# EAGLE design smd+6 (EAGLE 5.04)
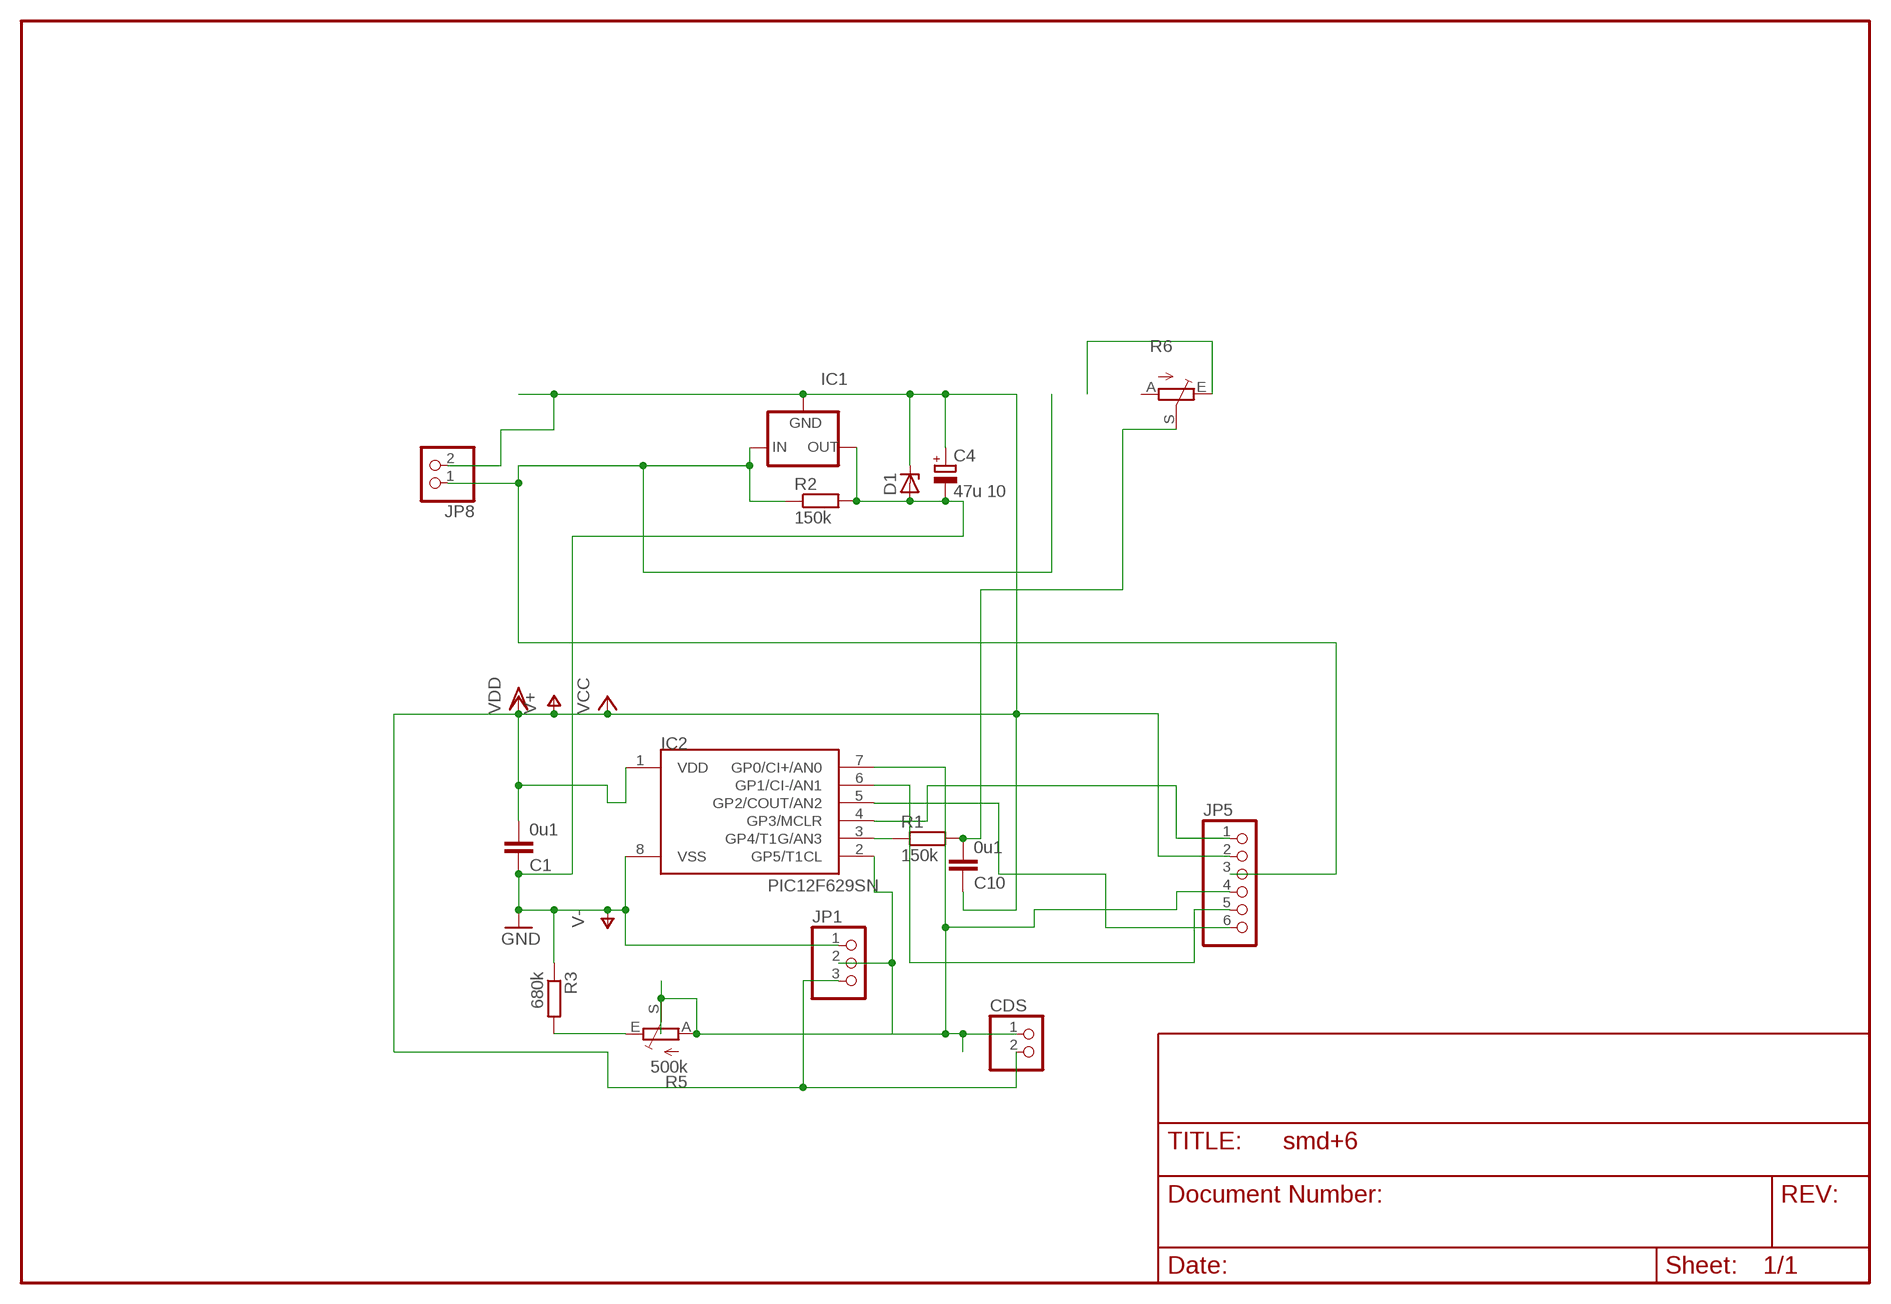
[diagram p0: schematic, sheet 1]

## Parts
C1  0u1  C-EUC1206  [C1206]
C4  47u 10  CPOL-EUE2.5-6  [E2,5-6]
C10  0u1  C-EUC1206  [C1206]
CDS  PINHD-1X2  [1X02]
D1  ZENER-DIODESOT23  [SOT23]
IC1  79LXX  [79LXX]
IC2  PIC12F629SN  [SO-08]
JP1  PINHD-1X3  [1X03]
JP5  PINHD-1X6  [1X06]
JP8  PINHD-1X2  [1X02]
R1  150k  R-EU_R0805  [R0805]
R2  150k  R-EU_0204/2V  [0204V]
R3  680k  R-EU_R1206  [R1206]
R5  500k  TRIM_EU-CA6V  [CA6V]
R6  TRIM_EU-CA6V  [CA6V]

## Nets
CDS: IC2.2(GP5/T1CL) JP1.2
N$1: C10.2 R1.2 R6.S
N$2: IC2.5(GP2/COUT/AN2) JP5.6
N$3: IC2.4(GP3/MCLR) JP5.1
N$4: CDS.1 IC2.7(GP0/CI+/AN0) JP5.4 R5.A R5.S
N$5: R3.2 R5.E
N$7: R6.E
N$8: IC2.3(GP4/T1G/AN3) R1.1
N$10: IC1.IN JP5.3 JP8.1 R2.1
N$15: IC2.6(GP1/CI-/AN1) JP5.5
V+: C1.2 C4.+ C10.1 CDS.2 D1.3(C) IC1.GND IC2.1(VDD) JP1.3 JP5.2 JP8.2 ; supply symbol labelled VCC, VDD
V-: C1.1 C4.- D1.1(A) IC1.OUT IC2.8(VSS) JP1.1 R2.2 R3.1 ; supply symbol labelled GND
Unconnected: R6.A

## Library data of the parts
C1 C10 = rcl:C-EU: CAPACITOR, European symbol
C4 = rcl:CPOL-EU: POLARIZED CAPACITOR, European symbol
CDS JP8 = pinhead:PINHD-1X2: PIN HEADER
D1 = diode-1:ZENER-DIODE: Z-Diode
IC1 = v-reg:79LXX: VOLTAGE REGULATOR
IC2 = microchip-3:PIC12F6*: uPC nW 1k Program Flash memory 2x Timer Comparator 10b A/D converter/ 4xIN
JP1 = pinhead(2):PINHD-1X3: PIN HEADER
JP5 = pinhead(2):PINHD-1X6: PIN HEADER
R1-R3 = rcl:R-EU_: RESISTOR, European symbol
R5 R6 = pot:TRIM_EU-: POTENTIOMETER

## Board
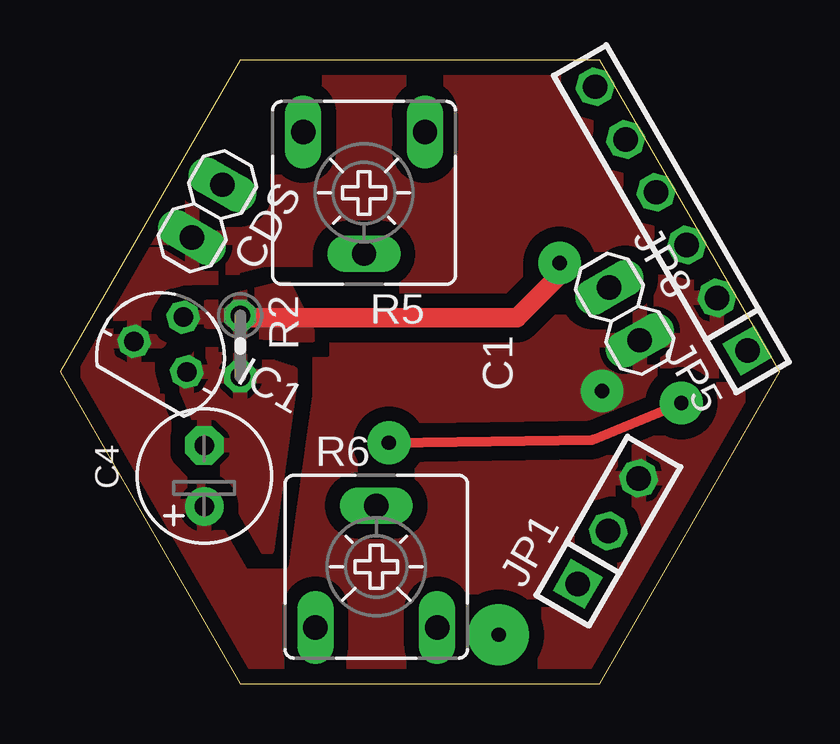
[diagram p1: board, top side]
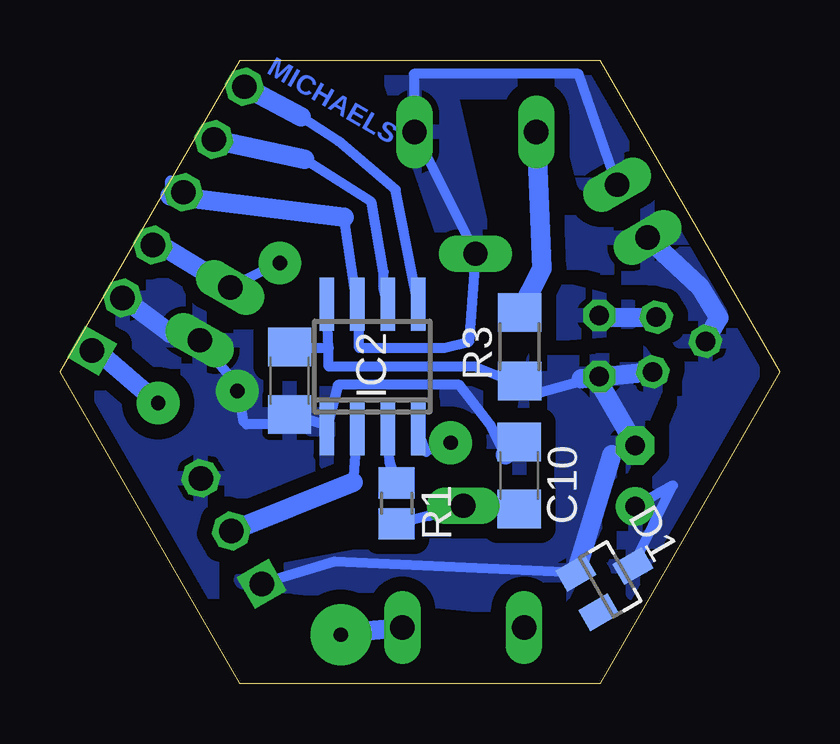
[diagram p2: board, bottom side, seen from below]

Size 30 x 25.98 mm. Coordinates in mm from the lower left corner, seen from the top.
Outline: 7.5,0 22.5,0 30,12.99 22.5,25.98 7.5,25.98 0,12.99 7.5,0
Copper layers (1*16): Top 0.035mm / dielectric 1.5mm / Bottom 0.035mm
Design rules "default *": minimum track width 10mil, minimum drill 24mil, track to track 8mil, track to pad 8mil, pad to pad 8mil, via to via 8mil, smd to smd 8mil, copper to edge 10mil, drill to drill 8mil, minimum pad ring 10mil, minimum via ring 8mil, stop-mask expansion 4mil, vias tented up to drill 0mil, thermal gap 10mil

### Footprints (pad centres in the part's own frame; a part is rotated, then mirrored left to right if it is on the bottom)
C1206 = smd 1.6 x 1.8: 1 -1.4,0; 2 1.4,0
E2,5-6 = drill 0.813 pad 1.6 round: + -1.27,0 | drill 0.813 pad 1.6 octagon: - 1.27,0
1X02 = drill 1.016 long: 1 -1.27,0; 2 1.27,0
SOT23 = smd 1 x 1.4: 1 -0.95,-1.1; 2 0.95,-1.1; 3 0,1.1
79LXX = drill 0.813 octagon: GND -1.27,0; IN 0,1.905; OUT 1.27,0
SO-08 = smd 0.6 x 2.2: 1 -1.905,-2.6; 2 -0.635,-2.6; 3 0.635,-2.6; 4 1.905,-2.6; 5 1.905,2.6; 6 0.635,2.6; 7 -0.635,2.6; 8 -1.905,2.6
1X03 = drill 1.016 square: 1 -2.54,0 | drill 1.016 octagon: 2 0,0; 3 2.54,0
1X06 = drill 1.016 square: 1 -6.35,0 | drill 1.016 octagon: 2 -3.81,0; 3 -1.27,0; 4 1.27,0; 5 3.81,0; 6 6.35,0
R0805 = smd 1.3 x 1.5: 1 -0.85,0; 2 0.85,0
0204V = drill 0.813 octagon: 1 -1.27,0; 2 1.27,0
R1206 = smd 1.6 x 1.803: 1 -1.422,0; 2 1.422,0
CA6V = drill 1.016 long: A -2.54,-2.54; E 2.54,-2.54; S 0,2.54

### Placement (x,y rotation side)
C1  20.42,12.62 270 bottom
C4  6.02,8.65 90 top
C10  10.85,8.66 270 bottom
CDS  6.14,19.68 240 top
D1  7.06,4.34 300 bottom
IC1  4.19,13.62 330 top
IC2  16.98,13.2 0 bottom
JP1  22.86,6.35 60 top
JP5  25.48,19.37 120 top
JP8  23.54,15.4 300 top
R1  15.96,7.51 270 bottom
R2  7.51,14.06 270 top
R3  10.84,14.03 90 bottom
R5  12.68,20.45 180 top
R6  13.19,4.87 0 top

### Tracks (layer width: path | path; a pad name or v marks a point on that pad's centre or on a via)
CDS
  Bottom 0.406: IC2.2 17.78,8.38
  Bottom 0.813: 17.78,8.38 JP1.2
N$1
  Bottom 0.406: 14.61,6.99 R6.S | C10.2 14.61,6.99 | 14.61,6.99 R1.2
N$2
  Bottom 0.406: 19.94,23.62 18.41,22.61 16,20.57 IC2.5
  Bottom 0.813: 19.94,23.62 JP5.6
N$3  (via drill 0.6 pad 1.78)
  Top 0.406: v13.72,10.03 22.23,10.16 v25.91,11.68
  Bottom 0.406: IC2.4 14.73,9.65 v13.72,10.03 | 28.57,13.97 JP5.1
  Bottom 0.813: v25.91,11.68 28.57,13.97
N$4
  Bottom 0.406: 18.16,19.43 IC2.7 17.53,14.86 17.53,13.97 13.97,13.97 12.95,14.22 R5.S R5.A 15.24,25.4 8.38,25.4 CDS.1 | 25.4,20.32 25.4,20.95 24.77,20.32 JP5.4
  Bottom 0.813: 18.16,19.43 25.4,20.32
  pour Bottom (isolate 0.61): 5.08,22.86 8.38,26.16 16.51,25.91 13.72,17.78 12.19,18.03 13.72,24.64 9.14,24.64 8.13,20.83
N$5
  Bottom 0.813: R3.2 9.91,17.27 R5.E
N$7
  Bottom 0.813: R6.E 17.65,2.16
N$8
  Bottom 0.406: IC2.3 16.26,9.27 R1.1
N$10  (via drill 0.6 pad 1.78)
  Top 0.406: R2.1 7.62,15.24
  Top 0.813: 7.62,15.24 19.05,15.24 20.83,17.02 v20.83,17.53
  Bottom 0.406: 26.04,18.41 JP5.3 | 7.62,15.24 R2.1 | JP8.1 v20.83,17.53 20.83,17.02
  Bottom 0.813: JP8.1 26.04,18.41 | IC1.IN 7.62,15.24
  pour Bottom (isolate 0.61): 5.33,15.49 6.86,14.73 10.41,14.48 9.4,16.51
  pour Top (isolate 0.61): 5.33,15.49 6.86,14.73 10.41,14.48 9.4,16.51
N$11  (via drill 0.6 pad 2.54)
  other vias: 18.29,2.03
N$15
  Bottom 0.406: 19.81,21.84 17.02,20.07 16.51,17.14 16.51,16.51 IC2.6
  Bottom 0.813: 19.81,21.84 JP5.5
V+  (via drill 0.6 pad 1.78)
  Bottom 0.406: 11.43,9.53 12.06,10.79 13.34,12.45 18.41,12.45 IC2.1 19.05,10.79 C1.2 20.32,10.79 22.23,10.79 22.35,10.92 22.61,12.45 JP8.2 25.4,14.48 25.4,14.61 | C4.+ 4.45,8.26 D1.3
  Bottom 0.813: 25.4,14.61 JP5.2 | C10.1 11.43,9.53 | CDS.2 3.3,16.51 2.54,15.24 IC1.GND
  other vias: 22.61,12.19
  pour Bottom (isolate 0.61, rank 6): 7.62,25.4 22.86,25.4 29.72,12.95 22.1,0.25 7.87,0.25 0.76,13.21
  pour Top (isolate 0.61, rank 6): 7.62,25.4 22.86,25.4 29.72,12.95 22.1,0.25 7.87,0.25 0.76,13.21
V-
  Bottom 0.406: 18.8,13.97 IC2.8 | C1.1 20.32,13.97 18.8,13.97 | R2.2 8.26,12.7 | R2.2 10,12.11 | 10,12.11 10.16,12.06 | 6.99,9.53 C4.- | 7.62,12.7 R2.2 | 18.8,13.97 18.8,13.21 12.7,13.21 10.25,12.21 | JP1.1 18.54,5.08 D1.1 | 10,12.11 10.25,12.21 | 10.25,12.21 R3.1
  Bottom 0.813: 8.26,12.7 IC1.OUT | D1.1 6.99,9.53 | C4.- 7.62,12.7
  pour Bottom (isolate 0.61, rank 2): 5.08,12.7 6.6,9.14 9.4,3.05 22.35,4.32 11.43,6.35 10.16,13.46 5.84,13.72
  pour Top (isolate 0.61, rank 2): 5.08,12.7 6.6,9.14 8.64,5.59 9.65,12.95 7.37,13.72 5.84,13.72

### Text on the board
Bottom: MICHAELS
